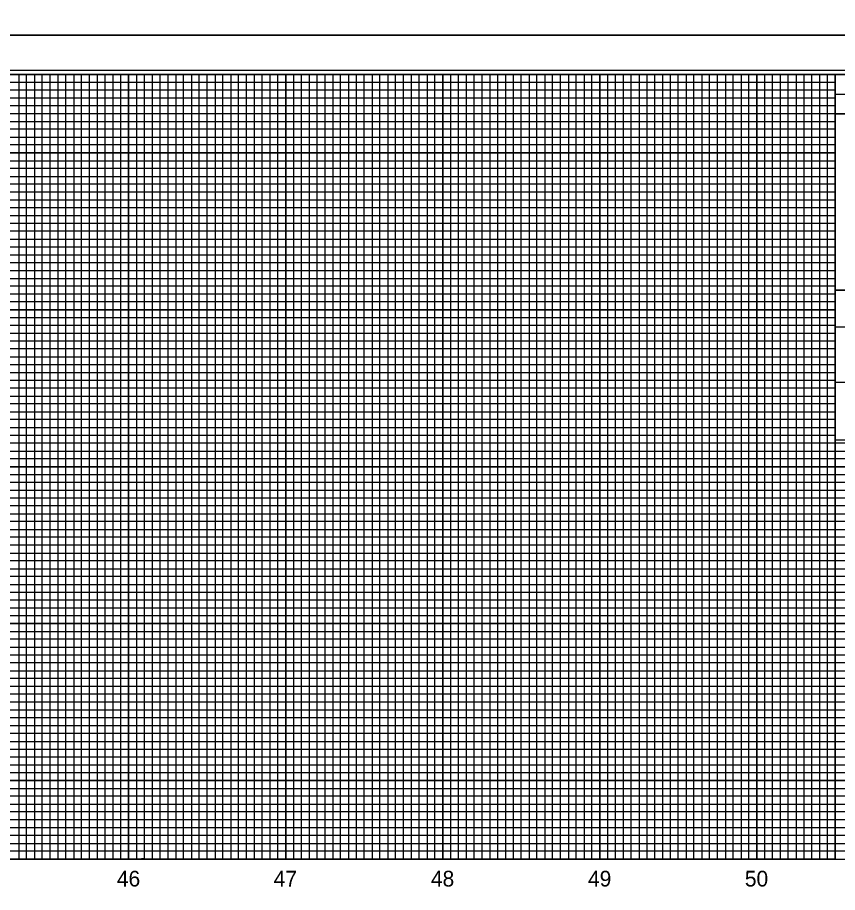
# Model space of a CAD drawing. Extents: x 1754992 to 1757273, y 732111 to 735411.
# Drawn here: x 1756127 to 1756649, y 733764 to 734322 of the extents above; entities that cross this region are included whole.
import ezdxf

# ---------------------------------------------------------------- set-up
doc = ezdxf.new("R2010")
doc.units = 0
for name, color, linetype in [('Old_Level_42', 7, 'Continuous'), ('Old_Level_43', 7, 'Continuous'), ('Scratch_Level_3', 7, 'Continuous'), ('Sheet Cutting Line CELL', 7, 'Continuous'), ('Sheet DOT Grid CELL', 7, 'Continuous'), ('Sheet Plot Border Inside CELL', 7, 'Continuous'), ('Sheet Plot Border Outside CELL', 7, 'Continuous'), ('Sheet Profile CELL', 7, 'Continuous'), ('Sheet Profile Grid Major CELL', 7, 'Continuous'), ('Sheet Profile Grid Middle CELL', 7, 'Continuous'), ('Sheet Profile Grid Minor CELL', 7, 'Continuous'), ('Sheet Sticker Exception Certification CELL', 7, 'Continuous')]:
    doc.layers.add(name, color=color, linetype=linetype)

msp = doc.modelspace()

# ---------------------------------------------------------------- linework, layer by layer
at = {"layer": 'Old_Level_42'}
msp.add_line((1756647.62, 734124.73), (1756647.62, 734148.23), dxfattribs=at)
msp.add_lwpolyline([(1756847.67, 734089.43), (1756647.62, 734089.43), (1756647.62, 734124.73)], dxfattribs=at)
at = {"layer": 'Old_Level_43'}
msp.add_lwpolyline([(1756847.68, 734052.66), (1756647.63, 734052.66), (1756647.63, 734089.43)], dxfattribs=at)
at = {"layer": 'Scratch_Level_3'}
msp.add_lwpolyline([(1755397.67, 733785.78), (1755397.67, 734285.78), (1756647.62, 734285.78), (1756647.63, 734052.66), (1756647.67, 733785.78)], close=True, dxfattribs=at)
at = {"layer": 'Sheet Cutting Line CELL'}
for p, q in [((1755180.67, 734310.78), (1756864.67, 734310.78)), ((1756864.67, 734310.78), (1755180.67, 734310.78))]:
    msp.add_line(p, q, dxfattribs=at)
at = {"layer": 'Sheet DOT Grid CELL'}
for p, q in [((1756147.67, 733785.78), (1756147.67, 734285.78)), ((1756197.67, 733785.78), (1756197.67, 734285.78)), ((1756247.67, 733785.78), (1756247.67, 734285.78)), ((1756297.67, 733785.78), (1756297.67, 734285.78)), ((1756347.67, 733785.78), (1756347.67, 734285.78)), ((1756397.67, 733785.78), (1756397.67, 734285.78)), ((1756447.67, 733785.78), (1756447.67, 734285.78)), ((1756497.67, 733785.78), (1756497.67, 734285.78)), ((1756547.67, 733785.78), (1756547.67, 734285.78)), ((1756597.67, 733785.78), (1756597.67, 734285.78)), ((1756647.62, 734235.78), (1755347.67, 734235.78)), ((1756647.62, 734185.78), (1755347.67, 734185.78)), ((1756647.67, 733785.78), (1756647.67, 734148.23)), ((1756647.67, 734135.78), (1755347.67, 734135.78)), ((1756647.63, 734085.78), (1755347.67, 734085.78)), ((1756847.67, 734035.78), (1755347.67, 734035.78)), ((1756847.67, 733985.78), (1755347.67, 733985.78)), ((1756847.67, 733935.78), (1755347.67, 733935.78)), ((1756847.67, 733885.78), (1755347.67, 733885.78)), ((1756847.67, 733835.78), (1755347.67, 733835.78))]:
    msp.add_line(p, q, dxfattribs=at)
at = {"layer": 'Sheet Plot Border Inside CELL'}
msp.add_lwpolyline([(1755193.67, 733233.23), (1756860.17, 733233.23), (1756860.17, 734288.33), (1755193.67, 734288.33)], close=True, dxfattribs=at)
at = {"layer": 'Sheet Plot Border Outside CELL'}
for points in [[(1755180.67, 734310.78), (1756864.67, 734310.78), (1756864.67, 735410.78), (1755180.67, 735410.78)], [(1755180.67, 733210.78), (1756864.67, 733210.78), (1756864.67, 734310.78), (1755180.67, 734310.78)]]:
    msp.add_lwpolyline(points, close=True, dxfattribs=at)
at = {"layer": 'Sheet Profile CELL'}
for p, q in [((1756647.62, 734273.23), (1756847.67, 734273.23)), ((1755347.67, 733785.78), (1756847.67, 733785.78))]:
    msp.add_line(p, q, dxfattribs=at)
for points in [[(1756847.67, 734285.78), (1755347.67, 734285.78), (1755347.67, 733235.78), (1756847.67, 733235.78)], [(1756647.62, 734285.78), (1756847.67, 734285.78), (1756847.67, 734260.73), (1756647.62, 734260.73)], [(1756647.62, 734260.73), (1756747.67, 734260.73), (1756747.67, 734148.23), (1756647.62, 734148.23)]]:
    msp.add_lwpolyline(points, close=True, dxfattribs=at)
at = {"layer": 'Sheet Profile Grid Major CELL'}
for points in [[(1756097.67, 733785.78), (1756147.67, 733785.78), (1756147.67, 734285.78), (1756197.67, 734285.78), (1756197.67, 733785.78), (1756247.67, 733785.78), (1756247.67, 734285.78), (1756297.67, 734285.78), (1756297.67, 733785.78), (1756347.67, 733785.78), (1756347.67, 734285.78), (1756397.67, 734285.78), (1756397.67, 733785.78), (1756447.67, 733785.78), (1756447.67, 734285.78), (1756497.67, 734285.78), (1756497.67, 733785.78), (1756547.67, 733785.78), (1756547.67, 734285.78), (1756597.67, 734285.78), (1756597.67, 733785.78), (1756647.67, 733785.78), (1756647.67, 734285.78), (1756673.97, 734285.78)], [(1755347.67, 734235.78), (1756647.67, 734235.78)], [(1756647.67, 734185.78), (1755347.67, 734185.78), (1755347.67, 734135.78), (1756647.67, 734135.78)], [(1756647.63, 734085.78), (1755347.67, 734085.78), (1755347.67, 734035.78), (1756847.67, 734035.78)], [(1756847.67, 733985.78), (1755347.67, 733985.78), (1755347.67, 733935.78), (1756847.67, 733935.78)], [(1756847.67, 733885.78), (1755347.67, 733885.78), (1755347.67, 733885.78), (1755347.67, 733835.78), (1756847.67, 733835.78)]]:
    msp.add_lwpolyline(points, dxfattribs=at)
at = {"layer": 'Sheet Profile Grid Middle CELL'}
msp.add_line((1755347.67, 734260.78), (1756647.62, 734260.78), dxfattribs=at)
for points in [[(1756122.67, 733785.78), (1756172.67, 733785.78), (1756172.67, 734285.78), (1756222.67, 734285.78), (1756222.67, 733785.78), (1756272.67, 733785.78), (1756272.67, 734285.78), (1756322.67, 734285.78), (1756322.67, 733785.78), (1756372.67, 733785.78), (1756372.67, 734285.78), (1756422.67, 734285.78), (1756422.67, 733785.78), (1756472.67, 733785.78), (1756472.67, 734285.78), (1756522.67, 734285.78), (1756522.67, 733785.78), (1756572.67, 733785.78), (1756572.67, 734285.78), (1756622.67, 734285.78), (1756622.67, 733785.78), (1756672.67, 733785.78), (1756672.67, 734052.66)], [(1756647.67, 734210.78), (1755347.67, 734210.78), (1755347.67, 734160.78), (1756647.67, 734160.78)], [(1756647.62, 734110.78), (1755347.67, 734110.78), (1755347.67, 734060.78), (1756647.63, 734060.78)], [(1756847.67, 734010.78), (1755347.67, 734010.78), (1755347.67, 733960.78), (1756847.67, 733960.78)], [(1756847.67, 733910.78), (1755347.67, 733910.78), (1755347.67, 733860.78), (1756847.67, 733860.78)], [(1756847.67, 733810.78), (1755347.67, 733810.78)]]:
    msp.add_lwpolyline(points, dxfattribs=at)
at = {"layer": 'Sheet Profile Grid Minor CELL'}
for p, q in [((1755397.67, 734280.78), (1756647.67, 734280.78)), ((1756647.67, 734275.78), (1755397.67, 734275.43)), ((1755397.67, 734270.78), (1756647.67, 734270.78)), ((1756647.62, 734150.78), (1755397.67, 734150.78)), ((1756647.67, 734145.78), (1755397.67, 734145.78)), ((1756647.67, 734140.78), (1755397.67, 734140.78)), ((1755397.67, 734130.78), (1756647.67, 734130.78)), ((1756647.67, 734125.78), (1755397.67, 734125.78)), ((1755397.67, 734120.78), (1756647.62, 734120.78)), ((1756647.62, 734100.78), (1755397.67, 734100.78)), ((1755397.67, 734095.78), (1756647.62, 734095.78)), ((1756647.63, 734075.78), (1755397.67, 734075.78)), ((1755397.67, 734070.78), (1756647.63, 734070.78)), ((1756797.67, 734050.78), (1755397.67, 734050.78)), ((1755397.67, 734045.78), (1756797.67, 734045.78)), ((1756797.67, 734040.78), (1755397.67, 734040.78)), ((1755397.67, 734030.78), (1756797.67, 734030.78)), ((1756797.67, 734025.78), (1755397.67, 734025.78)), ((1755397.67, 734020.78), (1756797.67, 734020.78)), ((1756797.67, 734015.78), (1755397.67, 734015.78)), ((1755397.67, 734005.78), (1756797.67, 734005.78)), ((1756797.67, 734000.78), (1755397.67, 734000.78)), ((1755397.67, 733995.78), (1756797.67, 733995.78)), ((1756797.67, 733990.78), (1755397.67, 733990.78)), ((1755397.67, 733980.78), (1756797.67, 733980.78)), ((1756797.67, 733975.78), (1755397.67, 733975.78)), ((1755397.67, 733970.78), (1756797.67, 733970.78)), ((1756797.67, 733965.78), (1755397.67, 733965.78)), ((1755397.67, 733955.78), (1756797.67, 733955.78)), ((1756797.67, 733950.78), (1755397.67, 733950.78)), ((1755397.67, 733945.78), (1756797.67, 733945.78)), ((1756797.67, 733940.78), (1755397.67, 733940.78)), ((1755397.67, 733930.78), (1756797.67, 733930.78)), ((1756797.67, 733925.78), (1755397.67, 733925.78)), ((1755397.67, 733920.78), (1756797.67, 733920.78)), ((1756797.67, 733915.78), (1755397.67, 733915.78)), ((1755397.67, 733905.78), (1756797.67, 733905.78)), ((1756797.67, 733900.78), (1755397.67, 733900.78)), ((1756797.67, 733895.78), (1755397.67, 733895.78)), ((1756797.67, 733890.78), (1755397.67, 733890.78)), ((1755397.67, 733880.78), (1756797.67, 733880.78)), ((1756797.67, 733875.78), (1755397.67, 733875.78)), ((1755397.67, 733870.78), (1756797.67, 733870.78)), ((1756797.67, 733865.78), (1755397.67, 733865.78)), ((1755397.67, 733855.78), (1756797.67, 733855.78)), ((1756797.67, 733850.78), (1755397.67, 733850.78)), ((1755397.67, 733845.78), (1756797.67, 733845.78)), ((1756797.67, 733840.78), (1755397.67, 733840.78)), ((1755397.67, 733830.78), (1756797.67, 733830.78)), ((1756797.67, 733825.78), (1755397.67, 733825.78)), ((1755397.67, 733820.78), (1756797.67, 733820.78)), ((1756797.67, 733815.78), (1755397.67, 733815.78)), ((1755397.67, 733805.78), (1756797.67, 733805.78)), ((1756797.67, 733800.78), (1755397.67, 733800.78)), ((1755397.67, 733795.78), (1756797.67, 733795.78))]:
    msp.add_line(p, q, dxfattribs=at)
for points in [[(1756117.67, 734285.78), (1756127.67, 734285.78), (1756127.67, 733785.78), (1756132.67, 733785.78), (1756132.67, 734285.78), (1756137.67, 734285.78), (1756137.67, 733785.78), (1756142.67, 733785.78), (1756142.67, 734285.78), (1756152.67, 734285.78), (1756152.67, 733785.78), (1756157.67, 733785.78), (1756157.67, 734285.78), (1756162.67, 734285.78), (1756162.67, 733785.78), (1756167.67, 733785.78), (1756167.67, 734285.78), (1756177.67, 734285.78), (1756177.67, 733785.78), (1756182.67, 733785.78), (1756182.67, 734285.78), (1756187.67, 734285.78), (1756187.67, 733785.78), (1756192.67, 733785.78), (1756192.67, 734285.78), (1756202.67, 734285.78), (1756202.67, 733785.78), (1756207.37, 733786.33), (1756207.67, 733785.78), (1756207.67, 734285.78), (1756212.67, 734285.78), (1756212.67, 733785.78), (1756217.67, 733785.78), (1756217.67, 734285.78), (1756227.67, 734285.78), (1756227.67, 733785.78), (1756232.67, 733785.78)], [(1756232.67, 733785.78), (1756232.67, 734285.78), (1756237.67, 734285.78), (1756237.67, 733785.78), (1756242.67, 733785.78), (1756242.67, 734285.78), (1756252.67, 734285.78), (1756252.67, 733785.78), (1756257.67, 733785.78), (1756257.67, 734285.78), (1756262.67, 734285.78), (1756262.67, 733785.78), (1756267.67, 733785.78), (1756267.67, 734285.78), (1756277.67, 734285.78), (1756277.67, 733785.78), (1756282.67, 733785.78), (1756282.67, 734285.78), (1756287.67, 734285.78), (1756287.67, 733785.78), (1756292.67, 733785.78), (1756292.67, 734285.78), (1756302.67, 734285.78), (1756302.67, 733785.78), (1756307.67, 733785.78), (1756307.67, 734285.78), (1756312.67, 734285.78), (1756312.67, 733785.78), (1756317.67, 733785.78), (1756317.67, 734285.78), (1756327.67, 734285.78), (1756327.67, 733785.78), (1756332.67, 733785.78), (1756332.67, 734285.78), (1756337.67, 734285.78), (1756337.67, 733785.78), (1756342.67, 733785.78), (1756342.67, 734285.78), (1756352.67, 734285.78), (1756352.67, 733785.78), (1756357.67, 733785.78), (1756357.67, 734285.78), (1756362.67, 734285.78), (1756362.67, 733785.78), (1756367.67, 733785.78), (1756367.67, 734285.78), (1756377.67, 734285.78), (1756377.67, 733785.78), (1756382.67, 733785.78), (1756382.67, 734285.78), (1756387.67, 734285.78), (1756387.67, 733785.78), (1756392.67, 733785.78), (1756392.67, 734285.78), (1756402.67, 734285.78), (1756402.67, 733785.78), (1756407.67, 733785.78), (1756407.67, 734285.78), (1756412.67, 734285.78), (1756412.67, 733785.78), (1756417.67, 733785.78), (1756417.67, 734285.78), (1756427.67, 734285.78), (1756427.67, 733785.78), (1756432.67, 733785.78), (1756432.67, 734285.78), (1756437.67, 734285.78), (1756437.67, 733785.78), (1756442.67, 733785.78), (1756442.67, 734285.78), (1756452.67, 734285.78), (1756452.67, 733785.78), (1756457.67, 733785.78), (1756457.67, 734285.78), (1756462.67, 734285.78), (1756462.67, 733785.78), (1756467.67, 733785.78), (1756467.67, 734285.78), (1756477.67, 734285.78), (1756477.67, 733785.78), (1756482.67, 733785.78), (1756482.67, 734285.78), (1756487.67, 734285.78), (1756487.67, 733785.78), (1756492.67, 733785.78), (1756492.67, 734285.78), (1756502.67, 734285.78), (1756502.67, 733785.78), (1756507.67, 733785.78), (1756507.67, 734285.78), (1756512.67, 734285.78), (1756512.67, 733785.78), (1756517.67, 733785.78), (1756517.67, 734285.78), (1756527.67, 734285.78), (1756527.67, 733785.78), (1756532.67, 733785.78), (1756532.67, 734285.78), (1756537.67, 734285.78), (1756537.67, 733785.78)], [(1756537.67, 733785.78), (1756542.67, 733785.78), (1756542.67, 734285.78), (1756552.67, 734285.78), (1756552.67, 733785.78), (1756557.67, 733785.78), (1756557.67, 734285.78), (1756562.67, 734285.78), (1756562.67, 733785.78), (1756567.67, 733785.78), (1756567.67, 734285.78), (1756577.67, 734285.78), (1756577.67, 733785.78), (1756582.67, 733785.78), (1756582.67, 734285.78), (1756587.67, 734285.78), (1756587.67, 733785.78), (1756592.67, 733785.78), (1756592.67, 734285.78), (1756602.67, 734285.78), (1756602.67, 733785.78), (1756607.67, 733785.78), (1756607.67, 734285.78), (1756612.67, 734285.78), (1756612.67, 733785.78), (1756617.67, 733785.78), (1756617.67, 734285.78), (1756627.67, 734285.78), (1756627.67, 733785.78), (1756632.67, 733785.78), (1756632.67, 734285.78), (1756637.67, 734285.78), (1756637.67, 733785.78), (1756642.67, 733785.78), (1756642.67, 734285.78), (1756652.67, 734285.78)], [(1756647.67, 734265.78), (1755397.67, 734265.78), (1755397.67, 734255.78), (1756647.67, 734255.78)], [(1756647.62, 734250.78), (1755397.67, 734250.78), (1755397.67, 734245.78), (1756647.67, 734245.78)], [(1756647.67, 734240.78), (1755397.67, 734240.78), (1755397.67, 734230.78), (1756647.67, 734230.78)], [(1756647.67, 734225.78), (1755397.67, 734225.78), (1755397.67, 734220.78), (1756647.67, 734220.78)], [(1756647.67, 734215.78), (1755397.67, 734215.78), (1755397.67, 734205.78), (1756647.67, 734205.78)], [(1756647.67, 734200.78), (1755397.67, 734200.78), (1755397.67, 734195.78), (1756647.67, 734195.78)], [(1756647.67, 734190.78), (1755397.67, 734190.78), (1755397.67, 734180.78), (1756647.67, 734180.78)], [(1756647.67, 734175.68), (1755397.77, 734175.68), (1755397.77, 734170.78), (1756647.67, 734170.78)], [(1756647.67, 734165.78), (1755397.67, 734165.78), (1755397.67, 734155.78), (1756647.67, 734155.78)], [(1756647.62, 734115.78), (1755397.67, 734115.78), (1755397.67, 734105.78), (1756647.62, 734105.78)], [(1756647.62, 734090.78), (1755397.67, 734090.78), (1755397.67, 734080.78), (1756647.63, 734080.78)], [(1756647.63, 734065.78), (1755397.67, 734065.78), (1755397.67, 734055.78), (1756647.63, 734055.78)], [(1756797.67, 733790.78), (1755397.67, 733790.78)]]:
    msp.add_lwpolyline(points, dxfattribs=at)
at = {"layer": 'Sheet Sticker Exception Certification CELL'}
for p, q in [((1756647.62, 734124.73), (1756647.62, 734148.23)), ((1756647.62, 734148.23), (1756847.66, 734148.23)), ((1756647.62, 734124.73), (1756647.62, 734148.23)), ((1756647.62, 734148.23), (1756847.66, 734148.23)), ((1756847.66, 734124.73), (1756647.62, 734124.73)), ((1756847.66, 734124.73), (1756647.62, 734124.73))]:
    msp.add_line(p, q, dxfattribs=at)

# ---------------------------------------------------------------- texts
at = {"layer": 'Scratch_Level_3'}
for s, p in [('46', (1756190.15, 733768.28)), ('47', (1756290.01, 733768.28)), ('48', (1756390.14, 733768.28)), ('49', (1756490.18, 733768.28)), ('50', (1756590.06, 733768.28))]:
    msp.add_text(s, height=10, dxfattribs=at).set_placement(p)

doc.saveas('drawing.dxf')
